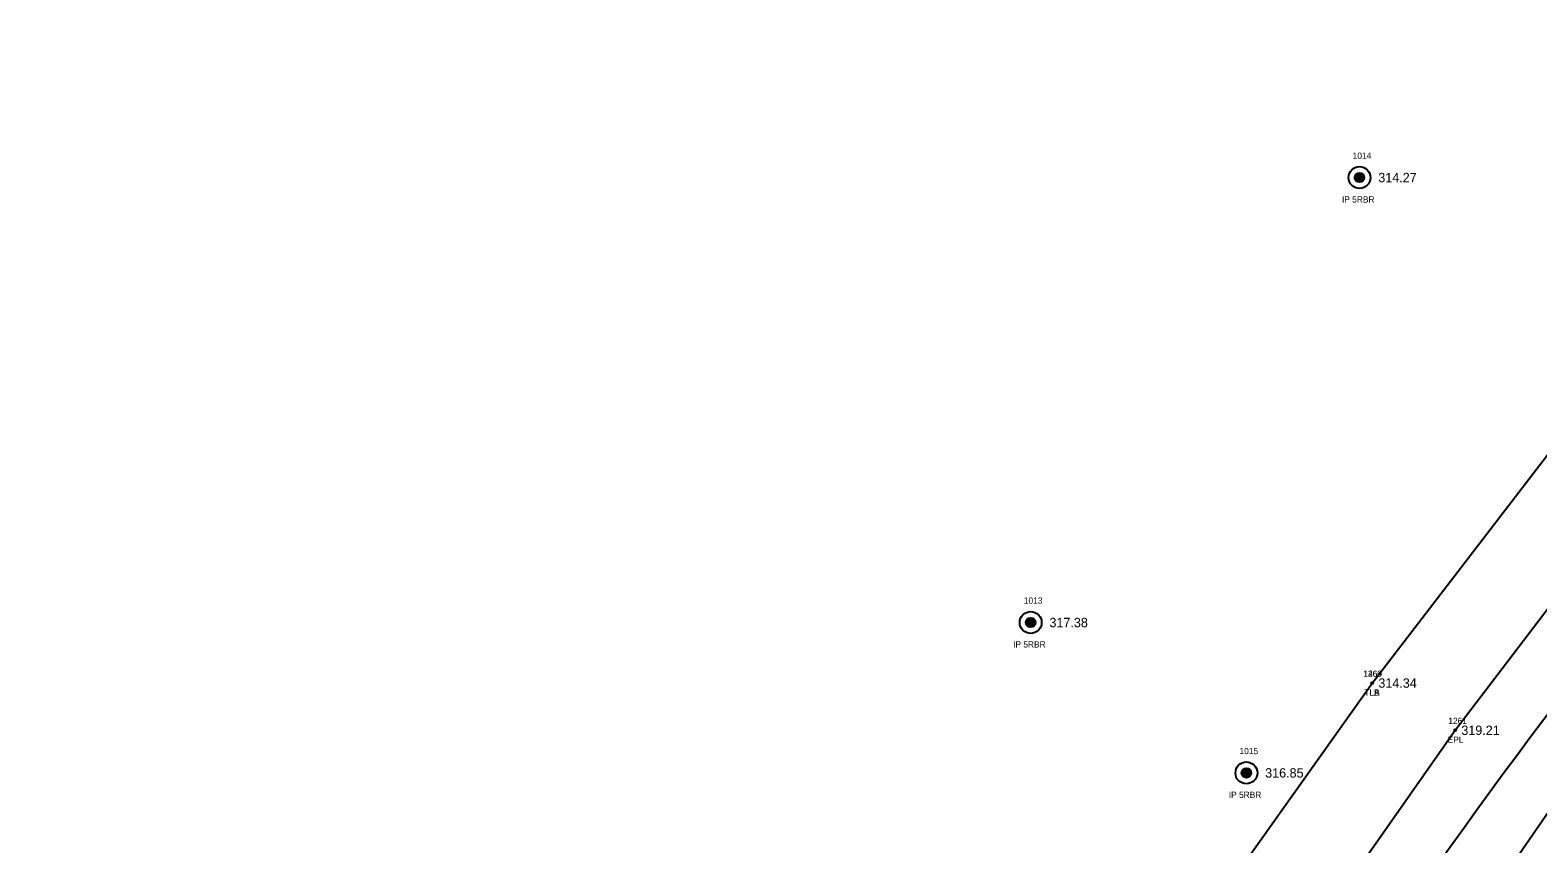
# Model space of a CAD drawing. Extents: x 1865045 to 1867370, y 910391 to 914218.
# Drawn here: x 1865884.1 to 1866125, y 912965.8 to 913095.9 of the extents above; entities that cross this region are included whole.
import ezdxf

# ---------------------------------------------------------------- set-up
doc = ezdxf.new("R2010")
doc.units = 0
for name, color, linetype in [('RD_EX_DV_Prop_txCode', 7, 'Continuous'), ('RD_EX_DV_PropPin', 7, 'Continuous'), ('RD_EX_Road', 7, 'Continuous'), ('RD_EX_Road_txCode', 7, 'Continuous'), ('RD_EX_TX_DV_Prop_ELEV', 7, 'Continuous'), ('RD_EX_TX_Road_ELEV', 7, 'Continuous'), ('RD_EX_TX_VEG_ELEV', 7, 'Continuous'), ('RD_EX_VEG', 7, 'Continuous'), ('RD_EX_VEG_txCode', 7, 'Continuous'), ('RD_HC_Cl', 7, 'Continuous'), ('RD_SMD_Locator', 7, 'Continuous')]:
    doc.layers.add(name, color=color, linetype=linetype)

msp = doc.modelspace()

# ---------------------------------------------------------------- linework, layer by layer
at = {"layer": 'RD_EX_DV_PropPin'}
for p, q in [((1866095.81, 913072.16), (1866095.81, 913072.55)), ((1866095.84, 913072.06), (1866095.84, 913072.66)), ((1866095.88, 913071.99), (1866095.88, 913072.73)), ((1866095.91, 913071.93), (1866095.91, 913072.78)), ((1866095.95, 913071.88), (1866095.95, 913072.83)), ((1866095.98, 913071.84), (1866095.98, 913072.87)), ((1866096.02, 913071.81), (1866096.02, 913072.91)), ((1866096.05, 913071.78), (1866096.05, 913072.94)), ((1866096.09, 913071.75), (1866096.09, 913072.97)), ((1866096.12, 913071.72), (1866096.12, 913072.99)), ((1866096.16, 913071.7), (1866096.16, 913073.01)), ((1866096.19, 913071.68), (1866096.19, 913073.03)), ((1866096.23, 913071.66), (1866096.23, 913073.05)), ((1866096.26, 913071.65), (1866096.26, 913073.06)), ((1866096.3, 913071.64), (1866096.3, 913073.08)), ((1866096.33, 913071.63), (1866096.33, 913073.09)), ((1866096.37, 913071.62), (1866096.37, 913073.1)), ((1866096.4, 913071.61), (1866096.4, 913073.11)), ((1866096.44, 913071.6), (1866096.44, 913073.11)), ((1866096.47, 913071.6), (1866096.47, 913073.12)), ((1866096.51, 913071.6), (1866096.51, 913073.12)), ((1866096.54, 913071.6), (1866096.54, 913073.12)), ((1866096.58, 913071.6), (1866096.58, 913073.12)), ((1866096.61, 913071.6), (1866096.61, 913073.12)), ((1866096.65, 913071.6), (1866096.65, 913073.11)), ((1866096.68, 913071.61), (1866096.68, 913073.11)), ((1866096.72, 913071.62), (1866096.72, 913073.1)), ((1866096.75, 913071.63), (1866096.75, 913073.09)), ((1866096.79, 913071.64), (1866096.79, 913073.08)), ((1866096.82, 913071.65), (1866096.82, 913073.06)), ((1866096.86, 913071.66), (1866096.86, 913073.05)), ((1866096.89, 913071.68), (1866096.89, 913073.03)), ((1866096.93, 913071.7), (1866096.93, 913073.01)), ((1866096.96, 913071.72), (1866096.96, 913072.99)), ((1866097, 913071.75), (1866097, 913072.97)), ((1866097.03, 913071.78), (1866097.03, 913072.94)), ((1866097.07, 913071.81), (1866097.07, 913072.91)), ((1866097.1, 913071.84), (1866097.1, 913072.87)), ((1866097.14, 913071.88), (1866097.14, 913072.83)), ((1866097.17, 913071.93), (1866097.17, 913072.78)), ((1866097.21, 913071.99), (1866097.21, 913072.73)), ((1866097.24, 913072.06), (1866097.24, 913072.66)), ((1866097.28, 913072.16), (1866097.28, 913072.55)), ((1866043.26, 913001.02), (1866043.26, 913001.41)), ((1866043.29, 913000.91), (1866043.29, 913001.51)), ((1866043.33, 913000.84), (1866043.33, 913001.58)), ((1866043.36, 913000.78), (1866043.36, 913001.64)), ((1866043.4, 913000.74), (1866043.4, 913001.69)), ((1866043.43, 913000.7), (1866043.43, 913001.73)), ((1866043.47, 913000.66), (1866043.47, 913001.76)), ((1866043.5, 913000.63), (1866043.5, 913001.79)), ((1866043.54, 913000.6), (1866043.54, 913001.82)), ((1866043.57, 913000.58), (1866043.57, 913001.85)), ((1866043.61, 913000.56), (1866043.61, 913001.87)), ((1866043.64, 913000.54), (1866043.64, 913001.89)), ((1866043.68, 913000.52), (1866043.68, 913001.9)), ((1866043.71, 913000.5), (1866043.71, 913001.92)), ((1866043.75, 913000.49), (1866043.75, 913001.93)), ((1866043.78, 913000.48), (1866043.78, 913001.94)), ((1866043.82, 913000.47), (1866043.82, 913001.95)), ((1866043.85, 913000.46), (1866043.85, 913001.96)), ((1866043.89, 913000.46), (1866043.89, 913001.97)), ((1866043.92, 913000.45), (1866043.92, 913001.97)), ((1866043.96, 913000.45), (1866043.96, 913001.97)), ((1866043.99, 913000.45), (1866043.99, 913001.97)), ((1866044.03, 913000.45), (1866044.03, 913001.97)), ((1866044.06, 913000.45), (1866044.06, 913001.97)), ((1866044.1, 913000.46), (1866044.1, 913001.97)), ((1866044.13, 913000.46), (1866044.13, 913001.96)), ((1866044.17, 913000.47), (1866044.17, 913001.95)), ((1866044.2, 913000.48), (1866044.2, 913001.94)), ((1866044.24, 913000.49), (1866044.24, 913001.93)), ((1866044.27, 913000.5), (1866044.27, 913001.92)), ((1866044.31, 913000.52), (1866044.31, 913001.9)), ((1866044.34, 913000.54), (1866044.34, 913001.89)), ((1866044.38, 913000.56), (1866044.38, 913001.87)), ((1866044.41, 913000.58), (1866044.41, 913001.85)), ((1866044.45, 913000.6), (1866044.45, 913001.82)), ((1866044.48, 913000.63), (1866044.48, 913001.79)), ((1866044.52, 913000.66), (1866044.52, 913001.76)), ((1866044.55, 913000.7), (1866044.55, 913001.73)), ((1866044.59, 913000.74), (1866044.59, 913001.69)), ((1866044.62, 913000.78), (1866044.62, 913001.64)), ((1866044.66, 913000.84), (1866044.66, 913001.58)), ((1866044.69, 913000.91), (1866044.69, 913001.51)), ((1866044.73, 913001.02), (1866044.73, 913001.41)), ((1866077.73, 912976.97), (1866077.73, 912977.36)), ((1866077.76, 912976.86), (1866077.76, 912977.46)), ((1866077.8, 912976.79), (1866077.8, 912977.53)), ((1866077.83, 912976.74), (1866077.83, 912977.59)), ((1866077.87, 912976.69), (1866077.87, 912977.64)), ((1866077.9, 912976.65), (1866077.9, 912977.68)), ((1866077.94, 912976.61), (1866077.94, 912977.71)), ((1866077.97, 912976.58), (1866077.97, 912977.74)), ((1866078.01, 912976.55), (1866078.01, 912977.77)), ((1866078.04, 912976.53), (1866078.04, 912977.8)), ((1866078.08, 912976.51), (1866078.08, 912977.82)), ((1866078.11, 912976.49), (1866078.11, 912977.84)), ((1866078.15, 912976.47), (1866078.15, 912977.85)), ((1866078.18, 912976.45), (1866078.18, 912977.87)), ((1866078.22, 912976.44), (1866078.22, 912977.88)), ((1866078.25, 912976.43), (1866078.25, 912977.89)), ((1866078.29, 912976.42), (1866078.29, 912977.9)), ((1866078.32, 912976.41), (1866078.32, 912977.91)), ((1866078.36, 912976.41), (1866078.36, 912977.92)), ((1866078.39, 912976.4), (1866078.39, 912977.92)), ((1866078.43, 912976.4), (1866078.43, 912977.92)), ((1866078.46, 912976.4), (1866078.46, 912977.92)), ((1866078.5, 912976.4), (1866078.5, 912977.92)), ((1866078.53, 912976.4), (1866078.53, 912977.92)), ((1866078.57, 912976.41), (1866078.57, 912977.92)), ((1866078.6, 912976.41), (1866078.6, 912977.91)), ((1866078.64, 912976.42), (1866078.64, 912977.9)), ((1866078.67, 912976.43), (1866078.67, 912977.89)), ((1866078.71, 912976.44), (1866078.71, 912977.88)), ((1866078.74, 912976.45), (1866078.74, 912977.87)), ((1866078.78, 912976.47), (1866078.78, 912977.85)), ((1866078.81, 912976.49), (1866078.81, 912977.84)), ((1866078.85, 912976.51), (1866078.85, 912977.82)), ((1866078.88, 912976.53), (1866078.88, 912977.8)), ((1866078.92, 912976.55), (1866078.92, 912977.77)), ((1866078.95, 912976.58), (1866078.95, 912977.74)), ((1866078.99, 912976.61), (1866078.99, 912977.71)), ((1866079.02, 912976.65), (1866079.02, 912977.68)), ((1866079.06, 912976.69), (1866079.06, 912977.64)), ((1866079.09, 912976.74), (1866079.09, 912977.59)), ((1866079.13, 912976.79), (1866079.13, 912977.53)), ((1866079.16, 912976.86), (1866079.16, 912977.46)), ((1866079.2, 912976.97), (1866079.2, 912977.36))]:
    msp.add_line(p, q, dxfattribs=at)
for centre, radius in [((1866096.54, 913072.36), 1.75), ((1866096.54, 913072.36), 0.761), ((1866043.99, 913001.21), 1.75), ((1866043.99, 913001.21), 0.761), ((1866078.46, 912977.16), 1.75), ((1866078.46, 912977.16), 0.761)]:
    msp.add_circle(centre, radius, dxfattribs=at)
at = {"layer": 'RD_EX_Road'}
for points in [[(1865903.57, 912372.96), (1865906.88, 912422.49), (1865912.53, 912474.19), (1865920.42, 912520.91), (1865929.82, 912572.99), (1865940.77, 912621.63), (1865955.24, 912671.64), (1865970.63, 912718.97), (1865989.1, 912764.11), (1866010.04, 912811.45), (1866032.39, 912856.52), (1866056.13, 912899.08), (1866083.33, 912943.32), (1866111.81, 912983.98), (1866142.7, 913024.56), (1866150.28, 913018.36)], [(1865923.15, 912371.34), (1865926.48, 912420.79), (1865932.54, 912471.22), (1865939.98, 912518.17), (1865949.78, 912568.96), (1865960.28, 912617.03), (1865973.33, 912665.05), (1865988.8, 912711.74), (1866006.22, 912756.19), (1866027.64, 912801.78), (1866050.43, 912847.27), (1866073.28, 912889.22), (1866100.01, 912932.18), (1866127.88, 912972.61), (1866158.18, 913011.47), (1866150.28, 913018.36)]]:
    msp.add_lwpolyline(points, dxfattribs=at)
at = {"layer": 'RD_EX_VEG'}
for points in [[(1866098.55, 912991.53), (1866170.46, 913085.22), (1866214.89, 913134.01), (1866248.8, 913179.2), (1866290.81, 913202.69), (1866329.39, 913241.23), (1866400.64, 913303.68), (1866444.61, 913326.92), (1866425.38, 913368.09)], [(1865884.1, 912555.57), (1865916.03, 912578.87), (1865923.6, 912626.66), (1865934.57, 912676.23), (1865952.17, 912724.15), (1865972.84, 912770.82), (1865993.29, 912819.49), (1866017.14, 912864.8), (1866071.43, 912953.35), (1866098.55, 912991.53)]]:
    msp.add_lwpolyline(points, dxfattribs=at)
at = {"layer": 'RD_HC_Cl'}
msp.add_arc((1866950.8, 912367.16), 1030.99, 140.51746, 166.19447, dxfattribs=at)
at = {"layer": 'RD_SMD_Locator'}
for centre in [(1866096.54, 913072.36), (1866043.99, 913001.21), (1866098.55, 912991.53), (1866098.55, 912991.53), (1866111.81, 912983.98), (1866078.46, 912977.16)]:
    msp.add_circle(centre, 0.15, dxfattribs=at)

# ---------------------------------------------------------------- texts
at = {"layer": 'RD_EX_DV_Prop_txCode'}
for s, p in [('1014', (1866095.44, 913075.36)), ('IP 5RBR', (1866093.73, 913068.36)), ('1013', (1866042.89, 913004.21)), ('IP 5RBR', (1866041.18, 912997.21)), ('1015', (1866077.36, 912980.16)), ('IP 5RBR', (1866075.65, 912973.16))]:
    msp.add_text(s, height=1, dxfattribs=at).set_placement(p)
at = {"layer": 'RD_EX_Road_txCode'}
for s, p in [('1261', (1866110.73, 912984.98)), ('EPL', (1866110.61, 912981.98))]:
    msp.add_text(s, height=1, dxfattribs=at).set_placement(p)
at = {"layer": 'RD_EX_TX_DV_Prop_ELEV'}
for s, p in [('314.27', (1866099.54, 913071.61)), ('317.38', (1866046.99, 913000.46)), ('316.85', (1866081.46, 912976.41))]:
    msp.add_text(s, height=1.5, dxfattribs=at).set_placement(p)
at = {"layer": 'RD_EX_TX_Road_ELEV'}
msp.add_text('319.21', height=1.5, dxfattribs=at).set_placement((1866112.81, 912983.23))
at = {"layer": 'RD_EX_TX_VEG_ELEV'}
msp.add_text('314.34', height=1.5, dxfattribs=at).set_placement((1866099.55, 912990.78))
msp.add_text('314.34', height=1.5, dxfattribs=at).set_placement((1866099.55, 912990.78))
at = {"layer": 'RD_EX_VEG_txCode'}
for s, p in [('1260', (1866097.14, 912992.53)), ('1464', (1866097.18, 912992.53)), ('TLA', (1866097.29, 912989.53)), ('TLB', (1866097.31, 912989.53))]:
    msp.add_text(s, height=1, dxfattribs=at).set_placement(p)

doc.saveas('drawing.dxf')
